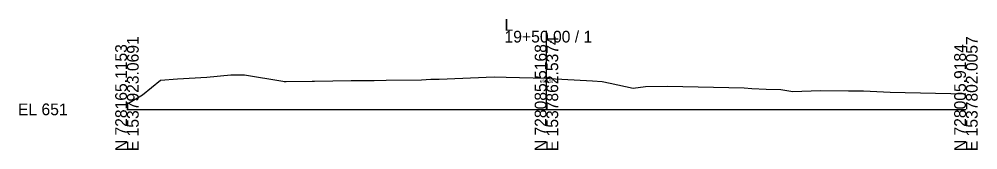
# Model space of a CAD drawing. Extents: x -26 to 1203, y -10 to 9522.
# Drawn here: x 974.3 to 1202.8, y 990.3 to 1021.6 of the extents above; entities that cross this region are included whole.
import ezdxf

# ---------------------------------------------------------------- set-up
doc = ezdxf.new("R2010")
doc.units = 0
for name, color, linetype in [('Default', 7, 'Continuous'), ('Exist Cross Section Cell', 7, 'Continuous'), ('Exist XS Center Line Elevation Label', 7, 'Continuous'), ('Exist XS Ground Line', 7, 'Continuous')]:
    doc.layers.add(name, color=color, linetype=linetype)

msp = doc.modelspace()

# ---------------------------------------------------------------- linework, layer by layer
at = {"layer": 'Exist Cross Section Cell'}
for p, q in [((1100, 1000), (1100, 1018.8)), ((1000, 1000), (1100, 1000)), ((1100, 1000), (1200, 1000))]:
    msp.add_line(p, q, dxfattribs=at)
at = {"layer": 'Exist XS Ground Line'}
msp.add_lwpolyline([(1000, 1001.27), (1003.71, 1003.5), (1007.97, 1006.97), (1012.07, 1007.29), (1019.03, 1007.69), (1024.73, 1008.23), (1027.99, 1008.24), (1037.17, 1006.72), (1037.48, 1006.66), (1037.96, 1006.67), (1044.12, 1006.78), (1044.69, 1006.78), (1053.45, 1006.9), (1058.96, 1006.91), (1061.79, 1007.01), (1070.23, 1007.09), (1072.47, 1007.19), (1074.46, 1007.25), (1087.52, 1007.78), (1090.4, 1007.69), (1100, 1007.44), (1100.75, 1007.42), (1110.97, 1006.83), (1113.29, 1006.68), (1115.23, 1006.3), (1120.71, 1005.07), (1123.63, 1005.45), (1128.89, 1005.56), (1147.11, 1005.15), (1148.96, 1005.01), (1152.39, 1004.82), (1155.87, 1004.72), (1158.74, 1004.31), (1165.24, 1004.49), (1172.01, 1004.4), (1175.61, 1004.43), (1181.92, 1004.09), (1200, 1003.73)], dxfattribs=at)

# ---------------------------------------------------------------- texts
at = {"layer": 'Default'}
msp.add_text('-', height=0.0001, dxfattribs=at).set_placement((1000, 1000))
msp.add_text('-', height=0.0001, dxfattribs=at).set_placement((1000, 1000))
msp.add_text('-', height=0.0001, dxfattribs=at).set_placement((1000, 1000))
at = {"layer": 'Exist Cross Section Cell'}
for s, p in [('L', (1090, 1018.8)), ('19+50.00 / 1', (1090, 1016)), ('EL 651', (974, 998.6))]:
    msp.add_text(s, height=2.8, dxfattribs=at).set_placement(p)
for s, p in [('E 1537923.0691', (1002.8, 990)), ('E 1537862.5374', (1102.8, 990)), ('E 1537802.0057', (1202.8, 990)), ('N 728165.1153', (1000, 990)), ('N 728085.5168', (1100, 990)), ('N 728005.9184', (1200, 990))]:
    msp.add_text(s, height=2.8, rotation=90, dxfattribs=at).set_placement(p)
at = {"layer": 'Exist XS Center Line Elevation Label'}
msp.add_text('658.44', height=0.75, dxfattribs=at).set_placement((1098.44, 1006.32))

doc.saveas('drawing.dxf')
